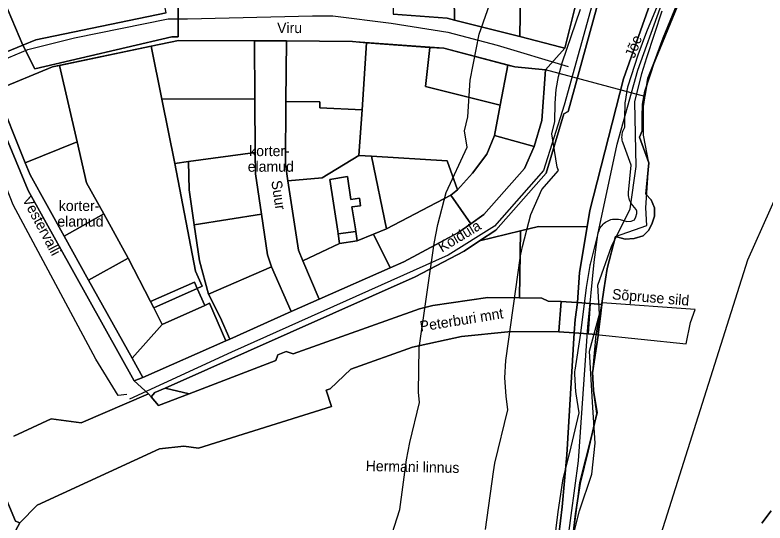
# Model space of a CAD drawing. Extents: x 728832 to 739469, y 6586263 to 6599699.
# Drawn here: x 738430.4 to 738858.8, y 6589449.5 to 6589739.5 of the extents above; entities that cross this region are included whole.
import ezdxf

# ---------------------------------------------------------------- set-up
doc = ezdxf.new("R2010")
doc.units = 0
for name, color, linetype in [('a_algatatud_dp', 7, 'Continuous'), ('a_kalda_ekv', 7, 'Continuous'), ('a_kalda_piiranguv', 7, 'Continuous'), ('a_kalda_veekaitsev', 7, 'Continuous'), ('a_piir', 7, 'Continuous'), ('a_veekogu_piir', 7, 'Continuous'), ('dp_hoonestus', 7, 'Continuous'), ('v_dp_kontaktvoond', 7, 'Continuous'), ('v_dp_situatsioon_tekst', 7, 'Continuous'), ('v_dp_tanav_tekst', 7, 'Continuous'), ('v_dp_tekst', 7, 'Continuous'), ('v_olol_transp_jjt', 7, 'Continuous')]:
    doc.layers.add(name, color=color, linetype=linetype)

msp = doc.modelspace()

# ---------------------------------------------------------------- linework, layer by layer
at = {"layer": 'a_algatatud_dp'}
for points in [[(738401.48, 6589846.18), (738409.6, 6589805.84), (738418.68, 6589760.61), (738422.22, 6589752.2), (738434.8, 6589722.31), (738441.65, 6589708.72), (738519.97, 6589727.04), (738523.67, 6589727.04), (738523.67, 6589741.29), (738523.41, 6589778.3), (738520.95, 6589778.06), (738518.24, 6589794.66), (738518.26, 6589795.24), (738488.12, 6589792.92), (738487.06, 6589799.47), (738474.97, 6589861.7), (738432.98, 6589854.33)], [(738401.48, 6589846.18), (738418.36, 6589850.55), (738432.98, 6589854.33), (738474.97, 6589861.7), (738487.06, 6589799.47), (738488.12, 6589792.92), (738498.81, 6589793.75), (738518.26, 6589795.24), (738518.24, 6589794.66), (738520.95, 6589778.06), (738523.41, 6589778.3), (738523.67, 6589741.29), (738523.67, 6589727.04), (738519.97, 6589727.04), (738441.65, 6589708.72), (738434.8, 6589722.31), (738422.22, 6589752.2), (738418.68, 6589760.61), (738409.6, 6589805.84)]]:
    msp.add_lwpolyline(points, close=True, dxfattribs=at)
at = {"layer": 'a_kalda_ekv'}
msp.add_lwpolyline([(738699.17, 6589445.68), (738703.64, 6589478.73), (738704.57, 6589483.7), (738711.86, 6589514.07), (738710.87, 6589521.94), (738710.27, 6589532.34), (738710.69, 6589542.31), (738719.22, 6589601.9), (738720.31, 6589607.34), (738725.02, 6589625.54), (738731.31, 6589639.95), (738740.85, 6589650.68), (738740.14, 6589652.63), (738737.13, 6589671.62), (738738.78, 6589678.64), (738738.91, 6589689.14), (738739.61, 6589696.89), (738740.87, 6589704.3), (738742.89, 6589712.2), (738753.43, 6589742.8)], dxfattribs=at)
at = {"layer": 'a_kalda_piiranguv'}
msp.add_lwpolyline([(738629.59, 6589392.84), (738650.28, 6589457.21), (738654.09, 6589485.43), (738655.95, 6589495.37), (738661.46, 6589518.31), (738660.81, 6589524.08), (738661.2, 6589549.39), (738669.73, 6589608.98), (738671.91, 6589619.86), (738676.62, 6589638.06), (738688.67, 6589663.95), (738687.17, 6589673.44), (738689.02, 6589681.37), (738690.37, 6589702.33), (738695.61, 6589728.48), (738706.15, 6589759.08)], dxfattribs=at)
at = {"layer": 'a_kalda_veekaitsev'}
for points in [[(738738.37, 6589437.11), (738740.66, 6589455.85), (738743.3, 6589473.51), (738743.35, 6589473.82), (738743.41, 6589474.13), (738743.48, 6589474.43), (738748.07, 6589492.97), (738752.61, 6589512.4), (738750.91, 6589523.28), (738750.86, 6589523.6), (738750.83, 6589523.92), (738750.81, 6589524.24), (738750.21, 6589534.64), (738750.19, 6589535.34), (738750.22, 6589536.04), (738750.3, 6589536.73), (738753.53, 6589557.91), (738756.79, 6589583.87), (738758.85, 6589596.44), (738758.91, 6589596.73), (738758.97, 6589597.02), (738759.04, 6589597.32), (738763.75, 6589615.52), (738764.01, 6589616.35), (738764.33, 6589617.17), (738764.73, 6589617.95), (738765.2, 6589618.69), (738765.73, 6589619.39), (738766.32, 6589620.04), (738766.96, 6589620.64), (738767.65, 6589621.17), (738768.39, 6589621.65), (738769.17, 6589622.06), (738769.98, 6589622.39), (738770.81, 6589622.66), (738771.67, 6589622.85), (738772.54, 6589622.97), (738773.41, 6589623.01), (738774.29, 6589622.97), (738775.16, 6589622.86), (738776.02, 6589622.67), (738779.87, 6589621.64), (738782.29, 6589621.79), (738784.3, 6589622.62), (738785.05, 6589624.27), (738785.67, 6589626.23), (738785.67, 6589627.4), (738785.19, 6589628.5), (738783.27, 6589630.7), (738782.7, 6589631.4), (738782.2, 6589632.16), (738781.77, 6589632.96), (738781.42, 6589633.79), (738781.14, 6589634.65), (738780.94, 6589635.53), (738780.82, 6589636.43), (738780.78, 6589637.34), (738780.83, 6589638.24), (738782.31, 6589653.77), (738777.71, 6589666.36), (738777.45, 6589667.18), (738777.26, 6589668.02), (738777.14, 6589668.87), (738777.1, 6589669.73), (738777.13, 6589670.59), (738777.24, 6589671.44), (738777.42, 6589672.28), (738777.66, 6589673.1), (738777.98, 6589673.9), (738778.71, 6589675.52), (738778.71, 6589681.09), (738778.91, 6589688.78), (738778.93, 6589689.25), (738778.98, 6589689.72), (738779.05, 6589690.19), (738780.31, 6589697.6), (738780.4, 6589698.07), (738780.51, 6589698.53), (738780.64, 6589698.99), (738786.33, 6589716.67), (738791.34, 6589730.04), (738803.47, 6589759.65)], [(738812.72, 6589755.86), (738800.7, 6589726.52), (738795.85, 6589713.6), (738790.16, 6589695.92), (738788.91, 6589688.51), (738788.71, 6589681.1), (738788.72, 6589673.38), (738787.1, 6589669.79), (738792.48, 6589655.08), (738790.78, 6589637.29), (738793.75, 6589633.91), (738795.66, 6589629.47), (738795.67, 6589624.7), (738794.41, 6589620.68), (738792.55, 6589616.62), (738789.13, 6589613.48), (738784.15, 6589611.88), (738778.86, 6589611.56), (738773.43, 6589613.01), (738768.72, 6589594.81), (738766.71, 6589582.63), (738765.68, 6589574.79), (738765.62, 6589574.29), (738764.58, 6589565.94), (738763.48, 6589557.03), (738763.44, 6589556.53), (738760.19, 6589535.22), (738760.79, 6589524.82), (738762.79, 6589512.02), (738757.79, 6589490.63), (738753.19, 6589472.03), (738750.59, 6589454.63), (738748.19, 6589435.04)], [(738856.95, 6589449.31), (738862.4, 6589456.36)]]:
    msp.add_lwpolyline(points, dxfattribs=at)
at = {"layer": 'a_piir'}
for points in [[(738816.58, 6589801.47), (738789.1, 6589772.13), (738772.21, 6589772.82), (738770.95, 6589773.79), (738746.35, 6589684.41), (738743.87, 6589682.99), (738733.85, 6589649.27), (738705.07, 6589616.72), (738695.73, 6589610.51), (738719.2, 6589616.31), (738729.37, 6589618.81), (738757.14, 6589618.51), (738758.7, 6589627.88), (738777.99, 6589702.96), (738795.34, 6589752.22)], [(738818.65, 6589803.67), (738816.58, 6589801.47), (738795.34, 6589752.22), (738777.99, 6589702.96), (738758.7, 6589627.88), (738757.14, 6589618.51), (738752.81, 6589592.39), (738751.65, 6589575.27), (738759.03, 6589574.73), (738765.66, 6589574.27), (738765.75, 6589575.1), (738768.64, 6589594.83), (738773.44, 6589613.05), (738791.32, 6589619.33), (738790.82, 6589629.42), (738792.48, 6589655.08), (738789.33, 6589670.8), (738789.33, 6589687.35), (738791.81, 6589703.4), (738807.87, 6589743.62), (738832.86, 6589803.2)], [(738645.6, 6589795.94), (738646.41, 6589740.05), (738677.32, 6589737.65), (738681.42, 6589736.61), (738680.72, 6589789.71)], [(738680.72, 6589789.71), (738681.42, 6589736.61), (738718.68, 6589727.2), (738719.27, 6589764.92), (738724.38, 6589781.99)], [(738508.25, 6589769.95), (738466.92, 6589761.42), (738444, 6589756.69), (738422.22, 6589752.2), (738434.8, 6589722.31), (738442.27, 6589725.35), (738516.71, 6589740.73), (738511.55, 6589765.74)], [(738753.47, 6589756.53), (738719.27, 6589764.92), (738718.68, 6589727.2), (738742.14, 6589721.17), (738744.47, 6589720.57)], [(738398.78, 6589745.38), (738412.05, 6589712.99), (738434.8, 6589722.31), (738422.22, 6589752.2), (738418.68, 6589760.61), (738397, 6589754.36)], [(738523.83, 6589724.98), (738508.21, 6589721.7), (738514.31, 6589691.53), (738567.42, 6589691.56), (738567.19, 6589724.76)], [(738567.19, 6589724.76), (738567.42, 6589691.56), (738567.62, 6589660.99), (738567.71, 6589648.87), (738571.19, 6589625.81), (738574.69, 6589602.56), (738576.85, 6589595.64), (738588.18, 6589570.27), (738604.19, 6589577.23), (738594.73, 6589599.12), (738592.36, 6589605.19), (738586.15, 6589644.89), (738584.89, 6589654.34), (738585.17, 6589690.1), (738585.42, 6589724.68)], [(738585.42, 6589724.68), (738585.17, 6589690.1), (738604.56, 6589689.86), (738604.42, 6589686.41), (738628.61, 6589685.32), (738629.41, 6589697.11), (738631.26, 6589723.68), (738623.17, 6589724.28)], [(738629.41, 6589697.11), (738628.61, 6589685.32), (738626.8, 6589659.19), (738633.94, 6589658.85), (738677.3, 6589656.14), (738683.17, 6589639.75), (738691.74, 6589649.13), (738699.95, 6589660.05), (738704.29, 6589670.72), (738707.6, 6589688.06), (738664.8, 6589698.7), (738667.4, 6589720.94), (738631.26, 6589723.68)], [(738508.21, 6589721.7), (738455.85, 6589710.7), (738465.9, 6589667.04), (738471.29, 6589643.69), (738481.14, 6589625.94), (738494.94, 6589600.69), (738507.79, 6589575.87), (738532.82, 6589586.94), (738534.48, 6589583.41), (738537.23, 6589584.63), (738533.42, 6589593.24), (738521.73, 6589654.73), (738514.31, 6589691.53)], [(738667.4, 6589720.94), (738664.8, 6589698.7), (738707.6, 6589688.06), (738711.95, 6589710.92), (738675.26, 6589720.49)], [(738451.79, 6589709.85), (738419.38, 6589696.58), (738436.27, 6589655.01), (738465.9, 6589667.04), (738455.85, 6589710.7)], [(738711.95, 6589710.92), (738707.6, 6589688.06), (738704.29, 6589670.72), (738726.89, 6589664.45), (738731.29, 6589679.26), (738733.43, 6589708.28), (738715.91, 6589709.94)], [(738419.38, 6589696.58), (738414.93, 6589694.42), (738437.9, 6589639.26), (738498.5, 6589530.65), (738503.41, 6589532.61), (738497.26, 6589543.58), (738472.37, 6589588.12), (738458.4, 6589613.29), (738439.01, 6589648.26), (738436.27, 6589655.01)], [(738514.31, 6589691.53), (738521.73, 6589654.73), (738529.39, 6589655.77), (738567.62, 6589660.99), (738567.42, 6589691.56)], [(738585.17, 6589690.1), (738584.89, 6589654.34), (738586.15, 6589644.89), (738605.8, 6589646.57), (738626.8, 6589659.19), (738628.61, 6589685.32), (738604.42, 6589686.41), (738604.56, 6589689.86)], [(738439.01, 6589648.26), (738458.4, 6589613.29), (738481.14, 6589625.94), (738471.29, 6589643.69), (738465.9, 6589667.04), (738436.27, 6589655.01)], [(738699.95, 6589660.05), (738691.74, 6589649.13), (738683.17, 6589639.75), (738679.26, 6589636.6), (738690.82, 6589620.31), (738698.28, 6589625.56), (738721.48, 6589651.81), (738726.89, 6589664.45), (738704.29, 6589670.72)], [(738567.62, 6589660.99), (738529.39, 6589655.77), (738529.92, 6589639.7), (738532.78, 6589619.63), (738571.19, 6589625.81), (738567.71, 6589648.87)], [(738626.8, 6589659.19), (738605.8, 6589646.57), (738586.15, 6589644.89), (738592.36, 6589605.19), (738594.73, 6589599.12), (738615.84, 6589609.07), (738614.99, 6589614.48), (738614.75, 6589615.99), (738610.21, 6589645.54), (738620.25, 6589647.2), (738622.14, 6589634.22), (738627.09, 6589634.92), (738627.76, 6589630.59), (738622.81, 6589629.88), (738624.84, 6589617.44), (738625.07, 6589615.93), (738625.89, 6589610.52), (738635.14, 6589614.4), (738642.64, 6589617.46), (738633.94, 6589658.85)], [(738677.3, 6589656.14), (738633.94, 6589658.85), (738642.64, 6589617.46), (738679.26, 6589636.6), (738683.17, 6589639.75)], [(738529.39, 6589655.77), (738521.73, 6589654.73), (738533.42, 6589593.24), (738537.23, 6589584.63), (738534.48, 6589583.41), (738538.84, 6589573.7), (738541.48, 6589574.88), (738550.86, 6589553.41), (738553.15, 6589554.45), (738547.59, 6589566.95), (738540.84, 6589580.14), (738535.72, 6589599.16), (738532.78, 6589619.63), (738529.92, 6589639.7)], [(738620.25, 6589647.2), (738610.21, 6589645.54), (738614.75, 6589615.99), (738614.99, 6589614.48), (738625.07, 6589615.93), (738624.84, 6589617.44), (738622.81, 6589629.88), (738627.76, 6589630.59), (738627.09, 6589634.92), (738622.14, 6589634.22)], [(738635.14, 6589614.4), (738644.67, 6589595.2), (738652.41, 6589598.61), (738683.42, 6589615.04), (738690.82, 6589620.31), (738679.26, 6589636.6), (738642.64, 6589617.46)], [(738481.14, 6589625.94), (738458.4, 6589613.29), (738472.37, 6589588.12), (738494.94, 6589600.69)], [(738571.19, 6589625.81), (738532.78, 6589619.63), (738535.72, 6589599.16), (738540.84, 6589580.14), (738576.85, 6589595.64), (738574.69, 6589602.56)], [(738719.2, 6589616.31), (738695.73, 6589610.51), (738687.02, 6589604.73), (738659.06, 6589589.93), (738516.14, 6589526.52), (738529.96, 6589523.28), (738579.39, 6589542.23), (738580.6, 6589545.48), (738585.23, 6589547.41), (738589.36, 6589546.05), (738661.37, 6589571.78), (738668.97, 6589573.65), (738700.54, 6589578.14), (738718.6, 6589577.98)], [(738614.99, 6589614.48), (738615.84, 6589609.07), (738625.89, 6589610.52), (738625.07, 6589615.93)], [(738729.37, 6589618.81), (738719.2, 6589616.31), (738718.6, 6589577.98), (738731.31, 6589577.86), (738734.96, 6589576.07), (738742.32, 6589575.93), (738751.05, 6589575.31), (738751.65, 6589575.27), (738752.81, 6589592.39), (738757.14, 6589618.51)], [(738615.84, 6589609.07), (738594.73, 6589599.12), (738604.19, 6589577.23), (738644.67, 6589595.2), (738635.14, 6589614.4), (738625.89, 6589610.52)], [(738514.52, 6589562.86), (738509.62, 6589572.29), (738507.79, 6589575.87), (738494.94, 6589600.69), (738472.37, 6589588.12), (738497.26, 6589543.58)], [(738576.85, 6589595.64), (738540.84, 6589580.14), (738547.59, 6589566.95), (738553.15, 6589554.45), (738588.18, 6589570.27)], [(738532.82, 6589586.94), (738507.79, 6589575.87), (738509.62, 6589572.29), (738534.48, 6589583.41)], [(738534.48, 6589583.41), (738509.62, 6589572.29), (738514.52, 6589562.86), (738538.84, 6589573.7)], [(738514.52, 6589562.86), (738497.26, 6589543.58), (738503.41, 6589532.61), (738550.86, 6589553.41), (738541.48, 6589574.88), (738538.84, 6589573.7)], [(738742.32, 6589575.93), (738741, 6589558.85), (738740.98, 6589558.61), (738749.77, 6589557.99), (738750.42, 6589565.63), (738751.65, 6589575.27), (738751.05, 6589575.31)], [(738751.65, 6589575.27), (738750.42, 6589565.63), (738749.77, 6589557.99), (738757.82, 6589557.43), (738759.03, 6589574.73)], [(738759.03, 6589574.73), (738757.82, 6589557.43), (738762.33, 6589557.12), (738765.66, 6589574.27)], [(738765.75, 6589575.1), (738765.66, 6589574.27), (738762.33, 6589557.12), (738813.71, 6589551.74), (738816.17, 6589563.99), (738818.92, 6589571.43)], [(738749.77, 6589557.99), (738745.6, 6589488.36), (738742.9, 6589458.64), (738740.06, 6589434.71), (738728.47, 6589399.2), (738712.92, 6589355.57), (738708.12, 6589342.15), (738676.04, 6589320.41), (738691.79, 6589302.01), (738703.88, 6589302.71), (738724.79, 6589362.3), (738731.52, 6589384.49), (738738.9, 6589403.33), (738748.31, 6589435.61), (738751.01, 6589455.1), (738753.02, 6589472.59), (738763.1, 6589512.27), (738761.08, 6589525.05), (738760.41, 6589535.8), (738762.33, 6589557.12), (738757.82, 6589557.43)], [(738276.05, 6589530.67), (738273.07, 6589520.88), (738264.37, 6589497.09), (738218.99, 6589514.16), (738213.31, 6589499.39), (738223.64, 6589480.33), (738225.13, 6589481.12), (738282.31, 6589459.96), (738305.05, 6589396.47), (738313.28, 6589399.33), (738339.92, 6589408.58), (738388.38, 6589425.39), (738417.71, 6589435.57), (738429.84, 6589439.77), (738430.85, 6589445.29), (738433.05, 6589449.51), (738430.63, 6589450.56), (738413.41, 6589491.43), (738415.44, 6589503.33), (738397.41, 6589495.04), (738380.39, 6589503.71), (738293.14, 6589479.77), (738279.67, 6589529.29)], [(738512.29, 6589516.51), (738529.96, 6589523.28), (738516.14, 6589526.52), (738510.34, 6589523.95), (738508.07, 6589521.47)]]:
    msp.add_lwpolyline(points, close=True, dxfattribs=at)
for points in [[(738753.47, 6589756.53), (738744.47, 6589720.57), (738733.43, 6589708.28), (738731.29, 6589679.26), (738726.89, 6589664.45), (738721.48, 6589651.81), (738698.28, 6589625.56), (738690.82, 6589620.31), (738683.42, 6589615.04), (738652.41, 6589598.61), (738644.67, 6589595.2), (738604.19, 6589577.23), (738588.18, 6589570.27), (738553.15, 6589554.45), (738550.86, 6589553.41), (738503.41, 6589532.61), (738498.5, 6589530.65), (738506.67, 6589523.12), (738508.07, 6589521.47), (738510.34, 6589523.95), (738516.14, 6589526.52), (738659.06, 6589589.93), (738687.02, 6589604.73), (738695.73, 6589610.51), (738705.07, 6589616.72), (738733.85, 6589649.27), (738743.87, 6589682.99), (738746.35, 6589684.41), (738770.95, 6589773.79)], [(738516.71, 6589740.73), (738442.27, 6589725.35), (738434.8, 6589722.31), (738412.05, 6589712.99)], [(738419.38, 6589696.58), (738451.79, 6589709.85), (738455.85, 6589710.7), (738508.21, 6589721.7), (738523.83, 6589724.98), (738567.19, 6589724.76), (738585.42, 6589724.68), (738623.17, 6589724.28), (738631.26, 6589723.68), (738667.4, 6589720.94), (738675.26, 6589720.49), (738711.95, 6589710.92), (738715.91, 6589709.94), (738733.43, 6589708.28), (738744.47, 6589720.57), (738742.14, 6589721.17), (738718.68, 6589727.2), (738681.42, 6589736.61), (738677.32, 6589737.65), (738646.41, 6589740.05)], [(738429.62, 6589498.93), (738451.12, 6589508.87), (738468.25, 6589506.63), (738506.67, 6589523.12), (738498.5, 6589530.65), (738437.9, 6589639.26), (738414.93, 6589694.42)], [(738413.41, 6589491.43), (738430.63, 6589450.56), (738433.05, 6589449.51), (738442.96, 6589459.68), (738512.98, 6589491.82), (738526.74, 6589493.32), (738535.2, 6589492.21), (738611.27, 6589515.9), (738608.11, 6589525.27), (738610.42, 6589526.06), (738622.16, 6589537.31), (738657.4, 6589549.81), (738685.51, 6589555.87), (738711.96, 6589558.64), (738741, 6589558.85), (738742.32, 6589575.93), (738734.96, 6589576.07), (738731.31, 6589577.86), (738718.6, 6589577.98), (738700.54, 6589578.14), (738668.97, 6589573.65), (738661.37, 6589571.78), (738589.36, 6589546.05), (738585.23, 6589547.41), (738580.6, 6589545.48), (738579.39, 6589542.23), (738529.96, 6589523.28), (738512.29, 6589516.51), (738508.07, 6589521.47), (738506.67, 6589523.12), (738468.25, 6589506.63), (738451.12, 6589508.87), (738429.62, 6589498.93)], [(738740.06, 6589434.71), (738742.9, 6589458.64), (738745.6, 6589488.36), (738749.77, 6589557.99), (738740.98, 6589558.61), (738741, 6589558.85), (738711.96, 6589558.64), (738685.51, 6589555.87), (738657.4, 6589549.81), (738622.16, 6589537.31), (738610.42, 6589526.06), (738608.11, 6589525.27), (738611.27, 6589515.9), (738535.2, 6589492.21), (738526.74, 6589493.32), (738512.98, 6589491.82), (738442.96, 6589459.68), (738433.05, 6589449.51), (738430.85, 6589445.29)]]:
    msp.add_lwpolyline(points, dxfattribs=at)
at = {"layer": 'a_veekogu_piir'}
for points in [[(738748.19, 6589435.04), (738750.59, 6589454.63), (738753.19, 6589472.03), (738757.79, 6589490.63), (738762.79, 6589512.02), (738760.79, 6589524.82), (738760.19, 6589535.22), (738763.44, 6589556.53), (738763.48, 6589557.03), (738764.58, 6589565.94), (738765.62, 6589574.29), (738765.68, 6589574.79), (738766.71, 6589582.63), (738768.72, 6589594.81), (738773.43, 6589613.01), (738778.86, 6589611.56), (738784.15, 6589611.88), (738789.13, 6589613.48), (738792.55, 6589616.62), (738794.41, 6589620.68), (738795.67, 6589624.7), (738795.66, 6589629.47), (738793.75, 6589633.91), (738790.78, 6589637.29), (738792.48, 6589655.08), (738787.1, 6589669.79), (738788.72, 6589673.38), (738788.71, 6589681.1), (738788.91, 6589688.51), (738790.16, 6589695.92), (738795.85, 6589713.6), (738800.7, 6589726.52), (738812.72, 6589755.86)], [(738862.4, 6589456.36), (738856.95, 6589449.31)]]:
    msp.add_lwpolyline(points, dxfattribs=at)
at = {"layer": 'dp_hoonestus'}
for points in [[(738544.55, 6591130.54), (738777.58, 6590706.02), (738824.58, 6590644.12), (738867.62, 6590606.55), (738942.09, 6590474.98), (739017.23, 6590295.07), (739034.11, 6590232.51), (739063.74, 6589965.72), (739039.57, 6589879.66), (738995.22, 6589833.98), (738899.89, 6589713.66), (738848.75, 6589599.46), (738792.31, 6589420.72)], [(738544.55, 6591130.54), (738777.58, 6590706.02), (738824.58, 6590644.12), (738867.62, 6590606.55), (738942.09, 6590474.98), (739017.23, 6590295.07), (739034.11, 6590232.51), (739063.74, 6589965.72), (739039.57, 6589879.66), (738995.22, 6589833.98), (738899.89, 6589713.66), (738848.75, 6589599.46), (738792.31, 6589420.72)], [(738745.31, 6589426.18), (738752.76, 6589456.47), (738759.87, 6589477.32), (738761.86, 6589495.03), (738760.37, 6589518.36), (738758.55, 6589547.49), (738764.18, 6589568.68), (738763.35, 6589585.23), (738771.13, 6589607.41), (738781.72, 6589628.92), (738785.19, 6589653.08), (738784.53, 6589689.83), (738788.5, 6589706.05), (738791.32, 6589715.31), (738800.09, 6589741.79)], [(738745.31, 6589426.18), (738752.76, 6589456.47), (738759.87, 6589477.32), (738761.86, 6589495.03), (738760.37, 6589518.36), (738758.55, 6589547.49), (738764.18, 6589568.68), (738763.35, 6589585.23), (738771.13, 6589607.41), (738781.72, 6589628.92), (738785.19, 6589653.08), (738784.53, 6589689.83), (738788.5, 6589706.05), (738791.32, 6589715.31), (738800.09, 6589741.79)]]:
    msp.add_lwpolyline(points, dxfattribs=at)
at = {"layer": 'v_dp_kontaktvoond'}
msp.add_lwpolyline([(738860.63, 6589942.5), (738858.24, 6589923.73), (738851.89, 6589911.28), (738844.44, 6589888.11), (738836, 6589849.88), (738834.18, 6589833.66), (738833.36, 6589816.28), (738833.85, 6589807.67), (738832.86, 6589803.2), (738791.81, 6589703.4), (738790.18, 6589692.87), (738733.43, 6589708.28), (738715.91, 6589709.94), (738675.26, 6589720.49), (738622.28, 6589724.29), (738523.83, 6589724.98), (738508.21, 6589721.7), (738451.79, 6589709.85), (738400.07, 6589688.32)], dxfattribs=at)
at = {"layer": 'v_olol_transp_jjt'}
for points in [[(738701.22, 6589304.96), (738722.43, 6589361.21), (738744.16, 6589429.66), (738746.01, 6589438.06), (738752.32, 6589484.93), (738757.68, 6589561.53), (738761.22, 6589598.39), (738763.23, 6589614.26), (738774.35, 6589665.72), (738786.24, 6589707.98), (738799.01, 6589743.38), (738822.48, 6589793.3), (738827.95, 6589808.63), (738827.95, 6589817.5), (738830.43, 6589848.34), (738832.8, 6589864.39), (738836.51, 6589886.76), (738847.81, 6589938.4), (738851.48, 6589981.51), (738853.67, 6590001.03), (738860.07, 6590020.16), (738885.77, 6590065.05), (738912.97, 6590120.99)], [(738494.3, 6589522.89), (738489.28, 6589522.16), (738476.64, 6589543.02), (738429.23, 6589631.12), (738404.91, 6589692.73), (738381.65, 6589749.21), (738371.67, 6589803.51), (738362.9, 6589856.18), (738346.3, 6590002.27), (738347.8, 6590019.69), (738347.8, 6590019.69), (738347.8, 6590019.69), (738347.8, 6590019.69), (738363.94, 6590093.67)], [(738739.83, 6590092.1), (738762.58, 6590052.49), (738765.8, 6590018.73), (738770.03, 6589999.23), (738765.16, 6589948.51), (738770.96, 6589801.22), (738770.96, 6589784.65), (738744.05, 6589687.94), (738732.19, 6589650.65), (738704.24, 6589618.95), (738677.81, 6589602.35), (738554.06, 6589547.05), (738495.74, 6589520.07)], [(738407.73, 6589696.77), (738422.16, 6589703.71), (738419.35, 6589712.26), (738437.74, 6589719.82), (738464.29, 6589726.37), (738517.92, 6589737.38), (738528.97, 6589737.38), (738600.32, 6589738.94), (738611.88, 6589738.94), (738645.28, 6589734.86), (738677.57, 6589729.69), (738705.8, 6589722.26), (738746.3, 6589710.17)]]:
    msp.add_lwpolyline(points, dxfattribs=at)

# ---------------------------------------------------------------- texts
at = {"layer": 'v_dp_situatsioon_tekst'}
for s, rotation, p in [('Sõpruse sild', 355.2099, (738771.28, 6589577.21)), ('Hermani linnus', 358.778, (738630.68, 6589479.13))]:
    msp.add_text(s, height=6, rotation=rotation, dxfattribs=at).set_placement(p)
at = {"layer": 'v_dp_tanav_tekst'}
msp.add_text('Viru', height=6, dxfattribs=at).set_placement((738580.11, 6589729.19))
for s, rotation, p in [('Jõe', 69.8444, (738784.27, 6589714.44)), ('Suur', 278.5485, (738576.75, 6589644.65)), ('Vestervalli', 297.8805, (738434.38, 6589634.18)), ('Koidula', 30.9767, (738674.26, 6589603.76)), ('Peterburi mnt', 9.1674, (738662.14, 6589558.72))]:
    msp.add_text(s, height=6, rotation=rotation, dxfattribs=at).set_placement(p)
at = {"layer": 'v_dp_tekst'}
for s, p in [('korter-', (738564.16, 6589658.91)), ('elamud', (738563.34, 6589650)), ('korter-', (738455.41, 6589627.6)), ('elamud', (738454.59, 6589618.69))]:
    msp.add_text(s, height=6, dxfattribs=at).set_placement(p)

doc.saveas('drawing.dxf')
